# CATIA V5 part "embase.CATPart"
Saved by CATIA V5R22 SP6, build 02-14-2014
Part number: embase
Bounding box of the stored display mesh (mm): x -75 to 75, y -90 to 90, z 0 to 78
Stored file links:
  C:\Users\kremer\Desktop\demo_5x\embase.CATPart
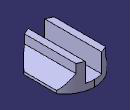
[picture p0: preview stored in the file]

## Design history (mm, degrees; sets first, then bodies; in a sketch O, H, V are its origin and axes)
Body1 (main body)
  Sketch1 on zx-plane, origin (0, 0, 0), H (-1, 0, 0), V (0, 0, 1)
    line L1 (-45, 78) -> (0, 78)
    line L2 (0, 0) -> (-75, 0)
    point P1 (0, 78)
    point P2 (0, 0.0001)
    point P3 (-75, 0)
    axis line L3 (0, 78) -> (0, 8.1088)
    point P5 (-75, 0)
    line L4 (-75, 0) -> (-75, 8)
    point P6 (-75, 8)
    line L5 (-75, 8) -> (-45, 51.6977)
    point P7 (-45, 51.6977)
    line L6 (-45, 51.6977) -> (-45, 78)
    point P8 (-45, 78)
    point P9 (-45, 78)
    line L7 (0, 78) -> (0, 0.0001)
    point P10 (0, 78)
    point P11 (-45, 51.6977)
    point P12 (0, 78)
    point P13 (0, 0)
    point P14 (-75, 0)
    point P15 (-75, 8)
    reference intersected line E1 through (0, 0) direction (0, -1) from yz-plane
    reference intersected line E2 through (0, 0) direction (-1, 0) from xy-plane
    distance L3 L6 = 45
    distance P2 P3 = 75
    distance P5 P6 = 8
    distance L1 L2 = 78
    distance L5 P2 = 66.3588
    distance P7 L2 = 51.6977
    horizontal: L1 H, L2 H
    vertical: L3 V, L4 V, L6 V, L7 V
    coincidence: P2 L3, P5 L2, P8 L6, P9 L1, P1 L3, P10 L1, P11 L5, P12 L7, P1 L1, P13 L7, P14 L2, P5 L4, P15 L5, P6 L4, P3 L4, P7 L6, P1 P12, P3 P14, P6 P15, P7 P11, P8 P9, E1 L3, L2 E2
    perpendicularity: L4 L2
  Pad1: profile Sketch1, direction (0, 1, 0), length 100, mirrored extent
  Sketch2 on xy-plane, origin (0, 0, 0), H (1, 0, 0), V (0, 1, 0)
    circle A1 centre (0, 0) radius 90
    point P1 (0, 0)
    reference intersected line E1 through (0, 0) direction (0, 1) from yz-plane
    reference intersected line E2 through (0, 0) direction (-1, 0) from zx-plane
    circle A2 centre (0, 0) radius 170.0048
    radius A1 = 90
    coincidence: P1 E1, P1 E2
  Pocket1: profile Sketch2, direction (0, 0, -1), through (limit type 3)
  Sketch3 on zx-plane, origin (0, 0, 0), H (-1, 0, 0), V (0, 0, 1)
    point P1 (0, 78)
    line L1 (0, 78) -> (-25, 78)
    line L2 (-25, 78) -> (-25, 20)
    line L3 (-25, 20) -> (0, 20)
    line L4 (0, 20) -> (0, 78)
    reference intersected line E1 (-45, 51.6977) -> (-45, 78) from face of Pad1 from Sketch1.L6
    reference projected line E2 (-75, 0) -> (0, 0) from edge [face of Pad1 from Sketch1.L2 | face of Pocket1 from Sketch2.A1]
    reference projected point E3 (0, 78) from edge [face of Pad1 from Sketch1.L1 | face of Pad1 from Sketch1.L7]
    distance E1 L2 = 20
    distance E2 L3 = 20
    horizontal: L1 H, L3 H
    vertical: L2 V, L4 V
    coincidence: P1 E3
  Pocket2: profile Sketch3, direction (0, -1, 0), through (limit type 3), opposite side through (limit type 3)
  Mirror1: of the body so far, about face of Pad1 from Sketch1.L7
